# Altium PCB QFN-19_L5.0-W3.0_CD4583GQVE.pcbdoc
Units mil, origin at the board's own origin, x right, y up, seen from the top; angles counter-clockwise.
Board outline 730.23 x 670.87 mil, 2 copper layers (Top Layer, Bottom Layer), stack 0 mil thick; 1 components, 0 nets, 18 pads, 0 vias.
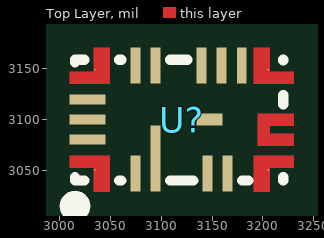
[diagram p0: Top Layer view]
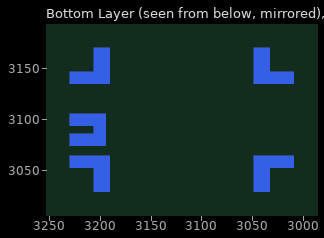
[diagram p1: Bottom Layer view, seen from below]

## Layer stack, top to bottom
Top Layer: signal copper (thickness not stored)
Bottom Layer: signal copper (thickness not stored)

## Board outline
3480.23,2750 2750,2750 2750,3420.87 3480.23,3420.87

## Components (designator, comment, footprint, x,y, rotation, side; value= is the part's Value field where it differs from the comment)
U? "" QFN-19_L5.0-W3.0_CD4583GQVE 3120,3100 r0 top

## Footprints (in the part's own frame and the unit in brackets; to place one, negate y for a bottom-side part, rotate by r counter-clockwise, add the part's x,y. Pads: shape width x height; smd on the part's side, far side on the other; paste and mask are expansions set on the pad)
QFN-19_L5.0-W3.0_CD4583GQVE [mm]
  round 0.033 smd: 1(-2.167,-1.25) 6(2.167,-1.25) 9(2.167,1.25) 15(-2.167,1.25)
  rect 0.25x0.9 smd: 2(-1.15,-1.35) 4(0.65,-1.35) 5(1.15,-1.35) 11(1,1.35) 12(0.5,1.35) 13(-0.65,1.35) 14(-1.15,1.35)
  rect 0.25x1.65 smd: 3(-0.65,-0.975)
  round 0 smd: 7(2.35,-0.25)
  rect 0.23x0.9 smd: 10(1.5,1.35)
  rect 0.9x0.25 smd: 16(-2.35,0.5) 17(-2.35,0) 18(-2.35,-0.5)
  rect 0.65x0.3 smd: 19(0.7,0)
  Top Layer region: -2.2,-0.9 -2.8,-0.9 -2.8,-1.2 -2.2,-1.2 -2.2,-1.8 -1.8,-1.8 -1.8,-0.9 -1.9,-0.9
  Top Layer region: -2.8,0.9 -2.2,0.9 -1.9,0.9 -1.8,0.9 -1.8,1.8 -2.2,1.8 -2.2,1.2 -2.8,1.2
  Top Layer region: 2.8,0.15 1.9,0.15 1.9,0.071 1.9,0.071 1.9,-0.579 1.9,-0.579 1.9,-0.65 2.8,-0.65 2.8,-0.35 2.2,-0.35 2.2,-0.15 2.8,-0.15
  Top Layer region: 2.8,0.9 2.2,0.9 1.9,0.9 1.8,0.9 1.8,1.8 2.2,1.8 2.2,1.2 2.8,1.2
  Top Layer region: 2.8,-0.9 2.2,-0.9 1.9,-0.9 1.8,-0.9 1.8,-1.8 2.2,-1.8 2.2,-1.2 2.8,-1.2
  Bottom Layer region: -2.2,-0.9 -2.8,-0.9 -2.8,-1.2 -2.2,-1.2 -2.2,-1.8 -1.8,-1.8 -1.8,-0.9 -1.9,-0.9
  Bottom Layer region: -2.8,0.9 -2.2,0.9 -1.9,0.9 -1.8,0.9 -1.8,1.8 -2.2,1.8 -2.2,1.2 -2.8,1.2
  Bottom Layer region: 2.8,0.15 1.9,0.15 1.9,0.071 1.9,0.071 1.9,-0.579 1.9,-0.579 1.9,-0.65 2.8,-0.65 2.8,-0.35 2.2,-0.35 2.2,-0.15 2.8,-0.15
  Bottom Layer region: 2.8,0.9 2.2,0.9 1.9,0.9 1.8,0.9 1.8,1.8 2.2,1.8 2.2,1.2 2.8,1.2
  Bottom Layer region: 2.8,-0.9 2.2,-0.9 1.9,-0.9 1.8,-0.9 1.8,-1.8 2.2,-1.8 2.2,-1.2 2.8,-1.2
  Multi-Layer region: -2.2,-0.9 -2.8,-0.9 -2.8,-1.2 -2.2,-1.2 -2.2,-1.8 -1.8,-1.8 -1.8,-0.9 -1.9,-0.9
  Multi-Layer region: -2.8,0.9 -2.2,0.9 -1.9,0.9 -1.8,0.9 -1.8,1.8 -2.2,1.8 -2.2,1.2 -2.8,1.2
  Multi-Layer region: 2.8,0.15 1.9,0.15 1.9,0.071 1.9,0.071 1.9,-0.579 1.9,-0.579 1.9,-0.65 2.8,-0.65 2.8,-0.35 2.2,-0.35 2.2,-0.15 2.8,-0.15
  Multi-Layer region: 2.8,0.9 2.2,0.9 1.9,0.9 1.8,0.9 1.8,1.8 2.2,1.8 2.2,1.2 2.8,1.2
  Multi-Layer region: 2.8,-0.9 2.2,-0.9 1.9,-0.9 1.8,-0.9 1.8,-1.8 2.2,-1.8 2.2,-1.2 2.8,-1.2
  silkscreen extent -3.05,-2.54 2.54,1.5

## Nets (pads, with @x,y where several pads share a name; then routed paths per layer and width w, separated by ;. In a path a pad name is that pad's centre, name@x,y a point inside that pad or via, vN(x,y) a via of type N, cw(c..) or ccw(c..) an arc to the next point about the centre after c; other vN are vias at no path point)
pads on no net: U?.1 U?.2 U?.3 U?.4 U?.5 U?.6 U?.7 U?.9 U?.10 U?.11 U?.12 U?.13 U?.14 U?.15 U?.16 U?.17 U?.18 U?.19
